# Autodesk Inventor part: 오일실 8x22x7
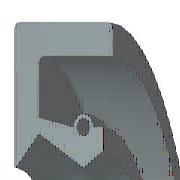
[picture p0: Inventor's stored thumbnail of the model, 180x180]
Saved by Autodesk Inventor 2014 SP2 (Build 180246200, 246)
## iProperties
IsCustomPart: 1
Company: 한국ATC센터
Created: 2014-07
Part Number: 오일실 8x22x7
Material: 고무
Description: 오일-실
Document SubType Name: Modeling
Standard: KS B 2804
Designer: KYOUNG IL JANG
Standards Organization: KS
Language: ko-KR
Size Designation: D - 8 22 7
Categories: <MemberInstance><Categories><Category DisplayName="샤프트 부품" InternalName="7f7aeb1f-a693-4053-b835-cee3144e0d98" Mnemonic="SHFT"><Category DisplayName="실링" Intern
Density: 0.93 g/cm^3
Appearance: 고무 - 검은색 - 버전 1.1
Author: KYOUNG IL JANG
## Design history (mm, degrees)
revolve "본체" stored, may be unused: angle "d17" = 90 deg
revolve "스프링1" stored, may be unused: angle "d18" = 90 deg
body "Solid1"
sketch "스케치1"
  geometry: L1 (0, 11)-(7, 11); L2 (7, 9.25)-(1.75, 9.25); L3 (1.75, 5.75)-(4.9, 4); L4 (4.9, 4)-(0, 4); L5 (0, 0)-(9.586, 0) reference; L6 (4.9, 4)-(6.3, 4.875); L7 (0, 18)-(0, -3) reference; L8 (-1.941, 0)-(11.507, 0) reference; L9 (4.2, 6.1)-(1.75, 6.59); L10 (1.75, 6.59)-(1.75, 9.25); L11 (0, 11)-(0, 4.088); L12 (4.9, 4)-(0, 4); L13 (1.75, 5.75)-(0.152, 4.028); L14 (7, 11)-(7, 9.25); L15 (5.6, 6.1)-(6.3, 6.1); L16 (6.3, 6.1)-(6.3, 4.875); C1 r 0.455 at (4.9, 6.1); A1 r 0.7 centre (4.9, 6.1) between (5.6, 6.1) and (4.2, 6.1); A2 r 0.088 centre (0.088, 4.088) between (0, 4.088) and (0.152, 4.028); 1 further point
  constraints: 28 end point, 5 horizontal alignment, 5 point on line, 4 point on circle, 4 vertical alignment, 3 centre point, 3 tangent, 2 collinear, 2 horizontal, 2 perpendicular, 1 coincident, 1 parallel
  dimensions: "d0" = 22 diameter of L1 L5 (= SD2); "d1" = 1.75 distance of L1.end L2.start (= SD); "d2" = 0.91 diameter of C1 (= SPDI); "d3" = 1.4 diameter of A1 (= SPDA); "d4" = 8 diameter of L3.end L5 (= NND); "d5" = 11.5 diameter of L3.start L5 (= TKDM); "d7" = 13.18 diameter of L9.end L5 (= TKDM + 0.24 x SWDT); "d8" = 1.75 distance between parallel lines of L11 L10 (= SD); "d9" = 4.9 distance from line of L11 C1.centre (= SPDST); "d10" = 12.2 diameter of C1.centre L5 (= HLDM); "d11" = 0.0875 radius of A2 (= 0.25 x LAB); "d12" = 6.3 distance between parallel lines of L11 L16 (= SDI); "d13" = 9.75 diameter of L6.end L5 (= ABDM); "d14" = 7 distance from line of L11 L1.end (= SWDT)
fillet "모깎기1" dims "d6" = 0.3 (= RR)
other parameters: "SD2" = 22 [user parameter; used in 1 equation term], "SWDT" = 7 [user parameter; used in 2 equation terms], "RR" = 0.3 [user parameter; used in 1 equation term], "SD" = 1.75 [user parameter; used in 2 equation terms], "NND" = 8 [user parameter; used in 1 equation term], "SPDA" = 1.4 [user parameter; used in 1 equation term], "SPDI" = 0.91 [user parameter; used in 1 equation term], "TKDM" = 11.5 [user parameter; used in 2 equation terms], "HLDM" = 12.2 [user parameter; used in 1 equation term], "ABDM" = 9.75 [user parameter; used in 1 equation term], "SDI" = 6.3 [user parameter; used in 1 equation term], "SPDST" = 4.9 [user parameter; used in 1 equation term], "LAB" = 0.35 [user parameter; used in 1 equation term], "d15" = 0, "d16" = 0, "d19" = 0
